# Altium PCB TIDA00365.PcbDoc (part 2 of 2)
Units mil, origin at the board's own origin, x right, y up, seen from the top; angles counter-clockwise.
Board outline 2520 x 2690 mil, 4 copper layers (Top Layer, Mid Layer, GND Layer, Bottom Layer), stack 69.2 mil thick; 170 components, 86 nets, 427 pads, 370 vias.
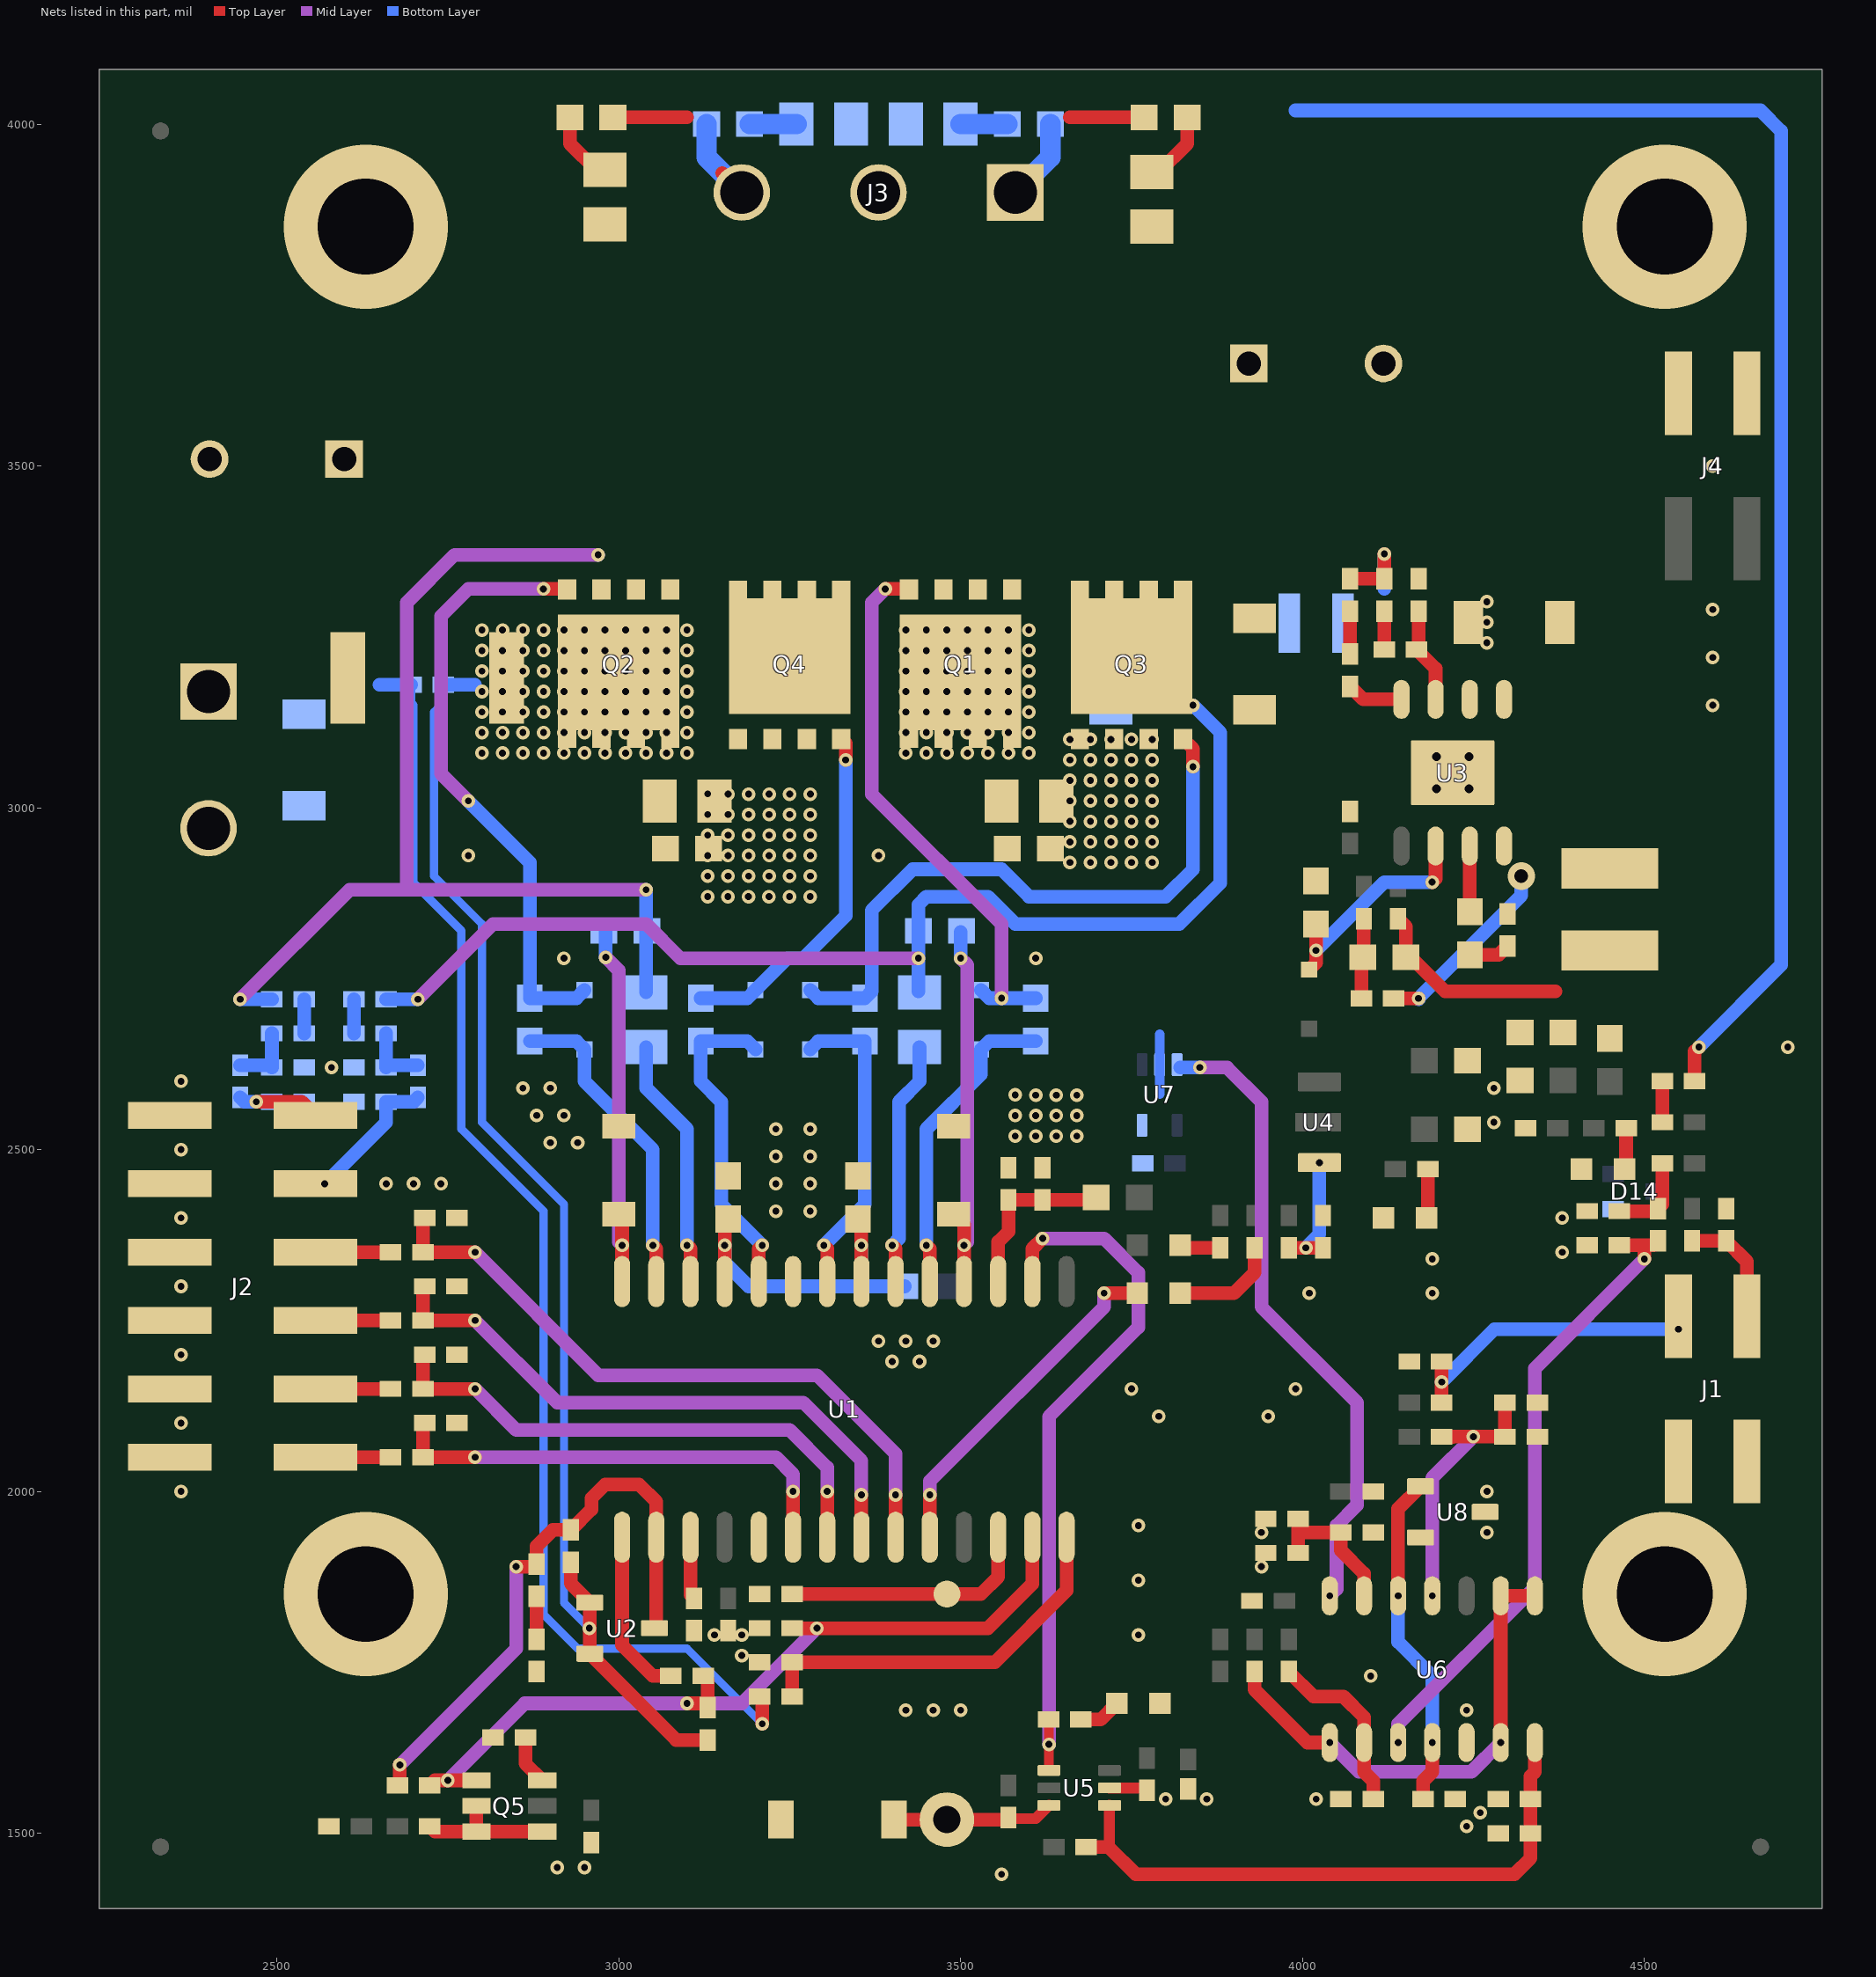
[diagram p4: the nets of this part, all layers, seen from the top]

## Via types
v1: diameter 20, hole 10, Top Layer to Bottom Layer, 355 vias
v2: diameter 40, hole 20, Top Layer to Bottom Layer, 7 vias
v3: diameter 240, hole 140, Top Layer to Bottom Layer, 4 vias
v4: diameter 25.98, hole 12.99, Top Layer to Bottom Layer, tented top, 4 vias

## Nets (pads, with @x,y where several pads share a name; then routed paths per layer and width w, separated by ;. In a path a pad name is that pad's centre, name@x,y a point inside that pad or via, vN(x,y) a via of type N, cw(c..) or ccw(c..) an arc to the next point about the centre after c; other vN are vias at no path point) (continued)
GND: C1.2 C2.2 C3.2 C4.2 C5.2 C10.2 C11.2 C12.2 C13.2 C16.2 C17.1 C18.2 C19.1 C22.1 C23.2 C24.2 C25.2 C26.1 C27.1 C28.1 C29.1 C30.2 C31.2 C32.2 C33.2 C37.2 C38.2 C39.2 C40.2 C41.2 C42.2 C43.2 C44.2 C45.2 C46.2 C47.2 C48.2 C49.2 C50.2 C51.2 D3.2 D4.2 D10.1 D11.1 D12.2 D13.1 D14.1 J1.1 J1.3 J2.1 J2.3 J2.5 J2.7 J2.9 J2.11 J3.2 J4.1 J4.3 J5.2 Q3.1 Q3.2 Q3.3 Q4.1 Q4.2 Q4.3 R10.2 R11.2 R19.1 R20.1 R21.1 R22.1 R24.1 R31.1 R32.1 R48.1 R51.1 R54.1 R61.1 R62.2 R63.1 R71.1 R72.1 SW1.1 U1.5 U1.23 U3.1 U3.9 U5.2 U6.12 U7.2 U7.5 U8.3 | length 145
  Top Layer w16: U5.2@3717.91,1566.38 3770,1566.38 C46.2@3773.62,1562.76
  Bottom Layer w14: 3791.11,2581.11 U7.2@3791.11,2624.24 3791.11,2668.89
  other v1: 3560,1440 2910,1450 2950,1450 4240,1510 4260,1530 3800,1550 3860,1550 4020,1550 3420,1680 3460,1680 3500,1680 4240,1680 4100,1730 3180,1760 3140,1790 3180,1790 3760,1790 3760,1870 3940,1890 3940,1940 4270,1940 3760,1950 2360,2000 4270,2000 2360,2100 3790,2110 3950,2110 3750,2150 3990,2150 3400,2190 3440,2190 2360,2200 3380,2220 3420,2220 3460,2220 4010,2290 4190,2290 2360,2300 4190,2340 4380,2350 2360,2400 4380,2400 3230,2410 3280,2410 2660,2450 2700,2450 2740,2450 3230,2450 3280,2450 3230,2490 3280,2490 2360,2500 2900,2510 2940,2510 3580,2519.74 3609.98,2519.74 3639.98,2519.74 3669.98,2519.74 3230,2530 3280,2530 4280,2540 2880,2550 2920,2550 3580,2549.74 3610,2549.74 3640,2549.74 3670,2549.74 3580,2580 3610,2579.74 3640,2579.74 3670,2579.74 2860,2590 2900,2590 4280,2590 2360,2600 2580,2620 4710,2650 2920,2780 3610,2780 3130,2870 3159.74,2870 3189.74,2870 3219.74,2870 3249.74,2870 3280,2870 3130,2900 3160,2900 3190,2900 3220,2900 3250,2900 3280.26,2900 3660,2920 3689.98,2920 3719.98,2920 3749.98,2920 3780.24,2920 2780,2930 3130,2930 3159.98,2930 3189.98,2930 3219.98,2930 3249.98,2930 3280.24,2930 3380,2930 3660,2950 3689.98,2950 3719.98,2950 3749.98,2950 3780.24,2950 3130,2960 3159.98,2960 3189.98,2960 3219.98,2960 3249.98,2960 3280.24,2960 3660,2980 3690,2980 3720,2980 3750,2980 3780.26,2980 3130,2990 3160,2990 3190,2990 3220,2990 3250,2990 3280.26,2990 3660,3010 3690,3010 3720,3010 3750,3010 3780.26,3010 3130,3020.26 3160,3020 3190,3020 3220,3020 3250,3020 3280.26,3020 3660,3040 3690,3040 3720,3040 3750,3040 3780.26,3040 3660,3070 3690,3070 3720,3070 3750,3070 3780.26,3070 3660,3100 3690,3100 3720,3100 3750,3100 3780.26,3100 4600,3150 4600,3220 4600,3290 4600,3500
  other v3: 2630,1850 4530,1850 2630,3850 4530,3850
  other v4: 4196.18,3027.68 4243.43,3027.68 4196.18,3074.92 4243.43,3074.92
HS_A: C31.1 R30.2 U1.7 | length 792.2
  Top Layer w20: C31.1@2716.38,2200 2713.62,2197.24 R30.2@2713.62,2150 v1(2790,2150) ; U1.7@3305,1932.99 v1(3305,2000)
  Mid Layer w20: v1(2790,2150) 2850,2090 3250,2090 3305,2035 v1(3305,2000)
HS_B: C32.1 R33.2 U1.8 | length 889.4
  Top Layer w20: C32.1@2716.38,2300 2713.62,2297.24 R33.2@2713.62,2250 v1(2790,2250) ; U1.8@3355,1932.99 v1(3355,1995)
  Mid Layer w20: v1(2790,2250) 2910,2130 3270,2130 3355,2045 v1(3355,1995)
HS_BOOT_A: C6.1 U1.26 | length 369.9
  Top Layer w20: v1(3100,2360) 3105,2355 U1.26@3105,2307.01
  Bottom Layer w20: C6.1@3040,2650 3040,2590 3100,2530 v1(3100,2360)
HS_BOOT_B: C7.1 U1.20 | length 361.6
  Top Layer w20: v1(3400,2360) 3405,2355 U1.20@3405,2307.01
  Bottom Layer w20: v1(3400,2360) 3410,2370 3410,2570 3440,2600 C7.1@3440,2650
HS_CSN: C10.1 C11.1 C12.1 C13.1 C20.2 C21.1 Q1.5 Q1.6 Q1.7 Q1.8 Q1.9 Q2.5 Q2.6 Q2.7 Q2.8 Q2.9 R1.1 R15.2 U2.1 U2.2 | length 1895.9
  Top Layer w20: C21.1@2930,1896.38 2930,1865.16 U2.1@2957.76,1837.4 U2.2@2957.76,1762.6 3083.98,1636.38 R15.2@3130,1636.38
  Bottom Layer w12: C20.2@2743.62,3180 2743.62,3153.62 2730,3140 2730,2900 2800,2830 2800,2540 2920,2420 2920,1837.09 v1(2957.09,1800)
  Bottom Layer w20: C20.2@2743.62,3180 2790,3180
  other v1: 2800,3080 2830,3080 2860,3080 2890,3080 2920,3080 2950,3080 2980,3080 3010,3080 3040,3080 3070,3080 3100,3080 3420,3080 3450,3080 3480,3080 3510,3080 3540,3080 3570,3080 3600,3080 2800,3110 2830,3110 2860,3110 2890,3110 2920,3110 2950,3110 2980,3110 3010,3110 3040,3110 3070,3110 3100,3110 3420,3110 3450,3110 3480,3110 3510,3110 3540,3110 3570,3110 3600,3110 2800,3140 2830,3140 2860,3140 2890,3140 2920,3140 2950,3140 2980,3140 3010,3140 3040,3140 3070,3140 3100,3140 3420,3140 3450,3140 3480,3140 3510,3140 3540,3140 3570,3140 3600,3140 2800,3170 2830,3170 2860,3170 2890,3170 2920,3170 2950,3170 2980,3170 3010,3170 3040,3170 3070,3170 3100,3170 3420,3170 3450,3170 3480,3170 3510,3170 3540,3170 3570,3170 3600,3170 2800,3200 2830,3200 2860,3200 2890,3200 2920,3200 2950,3200 2980,3200 3010,3200 3040,3200 3070,3200 3100,3200 3420,3200 3450,3200 3480,3200 3510,3200 3540,3200 3570,3200 3600,3200 2800,3230 2830,3230 2860,3230 2890,3230 2920,3230 2950,3230 2980,3230 3010,3230 3040,3230 3070,3230 3100,3230 3420,3230 3450,3230 3480,3230 3510,3230 3540,3230 3570,3230 3600,3230 2800,3260 2830,3260 2860,3260 2890,3260 2920,3260 2950,3260 2980,3260 3010,3260 3040,3260 3070,3260 3100,3260 3420,3260 3450,3260 3480,3260 3510,3260 3540,3260 3570,3260 3600,3260
HS_CSP: C1.1 C2.1 C3.1 C4.1 C5.1 C20.1 J5.1 L2.1 R1.2 R4.2 R5.2 R14.2 R65.2 | length 4074
  Top Layer w20: v1(3210,1660) R14.2@3210,1696.38 ; R65.2@4573.62,2600 4573.62,2643.62 v1(4580,2650)
  Bottom Layer w12: C20.1@2696.38,3180 2696.38,3153.62 2700,3150 2700,2890 2770,2820 2770,2530 2890,2410 2890,1820 2940,1770 3100,1770 v1(3210,1660)
  Bottom Layer w20: 2650,3180 C20.1@2696.38,3180 ; 3990,4020 4670,4020 4700,3990 4700,2770 v1(4580,2650)
HS_GATE_A: D1.1 R2.1 U1.27 | length 468.1
  Top Layer w20: v1(3050,2360) 3055,2355 U1.27@3055,2307.01
  Bottom Layer w20: R2.1@2870,2658.5 2938.19,2658.5 D1.1@2950,2646.69 2950,2600 3050,2500 v1(3050,2360)
HS_GATE_B: D2.1 R3.1 U1.19 | length 459.8
  Top Layer w20: v1(3450,2360) 3455,2355 U1.19@3455,2307.01
  Bottom Layer w20: v1(3450,2360) 3450,2530 3530,2610 D2.1@3530,2646.69 3541.81,2658.5 R3.1@3610,2658.5
HS_PHASE_A: D3.1 R6.1 U1.28 | length 567.9
  Top Layer w20: D3.1@3000,2405.53 3005,2400.53 v1(3005,2360) U1.28@3005,2307.01
  Mid Layer w20: v1(2981.11,2781.3) 3000,2762.41 3000,2365 v1(3005,2360)
  Bottom Layer w20: v1(2981.11,2781.3) R6.1@2981.11,2817.39
HS_PHASE_B: D4.1 R7.1 U1.18 | length 569.5
  Top Layer w20: D4.1@3490,2405.53 3505,2390.53 v1(3505,2360) U1.18@3505,2307.01
  Mid Layer w20: v1(3500,2780) 3510,2770 3510,2365 v1(3505,2360)
  Bottom Layer w20: v1(3500,2780) R7.1@3500,2818.5
IIN: R21.2 U1.3 | length 84.4
  Top Layer w20: R21.2@3105,1848.62 U1.3@3105,1932.99
IOUT: I_CS1.1 R20.2 U1.12 | length 369.7
  Top Layer w20: R20.2@3253.62,1850 3530,1850 3555,1875 U1.12@3555,1932.99
LS_A: C30.1 R29.2 U1.6 | length 694.9
  Top Layer w20: C30.1@2716.38,2100 2713.62,2097.24 R29.2@2713.62,2050 v1(2790,2050) ; U1.6@3255,1932.99 v1(3255,2000)
  Mid Layer w20: v1(2790,2050) 3230,2050 3255,2025 v1(3255,2000)
LS_B: C33.1 R34.2 U1.9 | length 986.7
  Top Layer w20: C33.1@2716.38,2400 2713.62,2397.24 R34.2@2713.62,2350 v1(2790,2350) ; U1.9@3405,1932.99 v1(3405,1995)
  Mid Layer w20: v1(2790,2350) 2970,2170 3290,2170 3405,2055 v1(3405,1995)
LS_GATE_A: D5.1 R8.1 U1.24 | length 475.9
  Top Layer w20: U1.24@3205,2307.01 3205,2355.29 3205.29,2355.29 v1(3210,2360)
  Bottom Layer w20: D5.1@3200,2646.69 3188.19,2658.5 R8.1@3120,2658.5 3120,2600 3150,2570 3150,2420 v1(3210,2360)
LS_GATE_B: D6.1 R9.2 U1.22 | length 463.3
  Top Layer w20: v1(3300,2360) 3305,2355 U1.22@3305,2307.01
  Bottom Layer w20: D6.1@3280,2646.69 3291.81,2658.5 R9.2@3360,2658.5 3360,2420 v1(3300,2360)
NetC8_1: C8.1 R4.1 | length 105.9
  Top Layer w20: C8.1@2928.5,4010 2928.5,3971.5 2966.8,3933.2 R4.1@2980,3933.2
NetC9_1: C9.1 R5.1 | length 107.3
  Top Layer w20: R5.1@3780,3930 3790.19,3930 3831.5,3971.3 C9.1@3831.5,4010
NetC14_1: C14.1 R10.1 | length 68.5
  Bottom Layer w30: C14.1@3191.5,4000 R10.1@3260,4000
NetC15_1: C15.1 R11.1 | length 68.5
  Bottom Layer w30: R11.1@3500,4000 C15.1@3568.5,4000
NetC16_1: C16.1 C18.1 R12.1 U1.17 | length 255.6
  Top Layer w20: U1.17@3555,2307.01 3555,2365 3570,2380 C16.1@3570,2426.38 C18.1@3620,2426.38 3694.88,2426.38 R12.1@3698.5,2430
NetC17_2: C17.2 C19.2 R13.1 U1.21 U1.25 | length 545.1
  Top Layer w20: U1.25@3155,2307.01 v1(3155,2360) 3155,2393.5 C17.2@3160,2398.5 ; C19.2@3350,2398.5 3355,2393.5 v1(3355,2360) U1.21@3355,2307.01
  Bottom Layer w20: v1(3155,2360) 3155,2335 3190,2300 R13.1@3418.5,2300 ; 3355,2305 v1(3355,2360)
NetC26_2: C26.2 J2.4 R35.1 | length 258.8
  Top Layer w20: J2.4@2537.5,2450 J2.4@2590,2450
  Bottom Layer w20: v1(2570,2450) 2660,2540 C26.2@2660,2570 2700,2570 R35.1@2706.38,2576.38
NetC27_2: C27.2 J2.2 R36.1 | length 143.6
  Top Layer w20: v1(2470,2570) 2536.3,2570 J2.2@2556.3,2550
  Bottom Layer w20: R36.1@2446.38,2576.38 2452.76,2570 v1(2470,2570) C27.2@2492.76,2570
NetC28_2: C28.2 J1.4 R37.1 | length 191.4
  Top Layer w20: R37.1@4570,2366.38 C28.2@4620,2366.38 4650,2336.38 J1.4@4650,2237.4
NetC29_2: C29.2 J1.2 R38.1 | length 438.4
  Top Layer w20: R38.1@4203.62,2130 v1(4203.62,2160) C29.2@4203.62,2190
  Bottom Layer w20: v1(4203.62,2160) 4281.02,2237.4 v1(4550,2237.4)
NetC34_1: C34.1 C37.1 L1.2 R43.1 R44.2 | length 300.4
  Top Layer w20: R44.2@4139.8,2837.68 4151.3,2826.18 C34.1@4151.3,2781.3 4158.7,2781.3 4208.7,2731.3 4369.8,2731.3
NetC34_2: C34.2 C36.1 R42.2 | length 117.9
  Top Layer w20: R42.2@4086.18,2721.3 4086.18,2779.17 C34.2@4088.31,2781.3 4089.8,2782.79 C36.1@4089.8,2837.68
NetC35_1: C35.1 U3.7 | length 96.2
  Top Layer w20: C35.1@4244.8,2847.8 U3.7@4244.8,2944.02
NetC35_2: C35.2 R41.1 | length 60.3
  Top Layer w20: C35.2@4244.8,2784.8 4286.93,2784.8 R41.1@4299.8,2797.68
NetC40_1: C40.1 L2.2 R46.1 R49.1 U3.2 | length 137.5
  Top Layer w20: R46.1@4069.8,3334.92 R49.1@4119.8,3334.92 v1(4119.8,3371.3)
  Bottom Layer w20: 4119.8,3320.2 v1(4119.8,3371.3)
  other v1: 4269.8,3241.3 4269.8,3271.3 4269.8,3301.3
NetC41_1: C41.1 D9.1 U3.6 | length 336.7
  Top Layer w20: D9.1@4010,2763.31 4019.8,2773.11 v1(4019.8,2791.38) C41.1@4019.8,2829.8 ; v1(4189.8,2891.3) 4194.8,2896.3 U3.6@4194.8,2944.02
  Bottom Layer w20: v1(4019.8,2791.38) 4119.73,2891.3 v1(4189.8,2891.3)
NetC45_1: C45.1 R60.2 R61.2 U6.4 | length 385.1
  Top Layer w20: 4220.39,2079.35 4219.74,2080 v1(4250,2080) R61.2@4296.38,2080 C45.1@4296.38,2130
  Mid Layer w20: v1(4190,1847.28) 4190,2020 v1(4250,2080)
NetC47_1: C47.1 R59.1 R63.2 U5.1 U6.14 | length 908.2
  Top Layer w16: 3717.91,1478.46 U5.1@3717.91,1540.79
  Top Layer w20: R59.1@3683.62,1480 3716.38,1480 ; 3717.91,1478.46 3756.38,1440 4310,1440 4333.62,1463.62 R63.2@4333.62,1500 C47.1@4333.62,1550 4333.62,1583.62 4340,1590 U6.14@4340,1632.72
NetD1_2: D1.2 Q2.4 R2.2 | length 898.6
  Top Layer w20: v1(2889.96,3320) 2923.81,3320 Q2.4@2924.51,3319.3
  Mid Layer w20: v1(2780,3010) 2740,3050 2740,3280 2780,3320 v1(2889.96,3320)
  Bottom Layer w20: v1(2780,3010) 2870,2920 R2.2@2870,2721.5 2938.19,2721.5 D1.2@2950,2733.31
NetD2_2: D2.2 Q1.4 R3.2 | length 805.2
  Top Layer w20: v1(3389.96,3320) 3423.81,3320 Q1.4@3424.51,3319.3
  Mid Layer w20: v1(3389.96,3320) 3370,3300.04 3370,3020 3560,2830 3560,2731.5 v1(3560,2721.5)
  Bottom Layer w20: D2.2@3530,2733.31 3541.81,2721.5 v1(3560,2721.5) R3.2@3610,2721.5
NetD5_2: D5.2 Q4.4 R8.2 | length 523.3
  Top Layer w20: Q4.4@3325.49,3100.7 3331.97,3094.22 v1(3331.97,3070)
  Bottom Layer w20: R8.2@3120,2721.5 3188.19,2721.5 D5.2@3200,2733.31 3246.69,2780 3270,2780 3331.97,2841.97 v1(3331.97,3070)
NetD6_2: D6.2 Q3.4 R9.1 | length 942.2
  Top Layer w20: Q3.4@3825.49,3100.7 3840,3086.19 v1(3840,3060)
  Bottom Layer w20: D6.2@3280,2733.31 3291.81,2721.5 R9.1@3360,2721.5 3370,2731.5 3370,2850 3430,2910 3560,2910 3600,2870 3800,2870 3840,2910 v1(3840,3060)
NetD7_2: D7.2 R39.1 | length 157.3
  Top Layer w20: D7.2@3821.5,2290 3900,2290 3930,2320 R39.1@3930,2356.38
NetD8_2: D8.2 R40.1 | length 60
  Top Layer w20: D8.2@3821.5,2360 3825.12,2356.38 R40.1@3880,2356.38
NetD10_2: D10.2 R45.1 | length 60.9
  Top Layer w20: D10.2@4471.3,2471.3 4473.43,2473.43 R45.1@4473.43,2531.3
NetD11_2: D11.2 R53.1 | length 66.4
  Top Layer w20: D11.2@4183.43,2404.92 R53.1@4183.43,2471.3
NetD13_2: D13.2 R64.2 | length 62.4
  Top Layer w20: R64.2@3675.91,1666.38 3704.88,1666.38 D13.2@3728.5,1690
NetJ2_6: J2.6 R34.1 | length 128.9
  Top Layer w20: J2.6@2537.5,2350 R34.1@2666.38,2350
NetJ2_8: J2.8 R33.1 | length 128.9
  Top Layer w20: J2.8@2537.5,2250 R33.1@2666.38,2250
NetJ2_10: J2.10 R30.1 | length 128.9
  Top Layer w20: J2.10@2537.5,2150 R30.1@2666.38,2150
NetJ2_12: J2.12 R29.1 | length 128.9
  Top Layer w20: J2.12@2537.5,2050 R29.1@2666.38,2050
NetL1_1: L1.1 R41.2 R42.1 U3.8 | length 278.1
  Top Layer w20: R42.1@4133.43,2721.3 v1(4169.8,2721.3)
  Bottom Layer w20: v1(4169.8,2721.3) 4320,2871.5 v2(4320,2900) ; v1@4170,2720 v1@4170.55,2720.55
NetQ5_2: Q5.2 Q5.3 Q5.4 R23.1 | length 205.1
  Top Layer w20: R23.1@2723.62,1510 2731.02,1502.6 Q5.3@2791.77,1502.6 ; Q5.2@2791.77,1540 Q5.3@2791.77,1502.6 ; Q5.4@2888.23,1502.6 Q5.3@2791.77,1502.6
NetQ5_6: Q5.6 R24.2 | length 72.8
  Top Layer w20: R24.2@2863.62,1640 2863.62,1602.01 Q5.6@2888.23,1577.4
NetR18_2: R18.2 R19.2 | length 62.8
  Top Layer w20: R19.2@2880,1783.62 R18.2@2880,1846.38
NetR25_1: R25.1 R27.2 | length 50
  Bottom Layer w20: R27.2@2612.76,2670 R25.1@2612.76,2720
NetR26_1: R26.1 R28.2 | length 50
  Bottom Layer w20: R28.2@2540,2670 R26.1@2540,2720
NetR27_1: R27.1 R31.2 R35.2 | length 92.8
  Bottom Layer w20: R31.2@2660,2620 R27.1@2660,2670 ; R31.2@2663.62,2623.62 R35.2@2706.38,2623.62
NetR28_1: R28.1 R32.2 R36.2 | length 92.8
  Bottom Layer w20: R36.2@2446.38,2623.62 R32.2@2489.13,2623.62 ; R32.2@2492.76,2620 R28.1@2492.76,2670
NetR46_2: R46.2 R47.1 | length 62.8
  Top Layer w20: R47.1@4069.8,3224.92 R46.2@4069.8,3287.68
NetR47_2: R47.2 U3.4 | length 82.9
  Top Layer w20: R47.2@4069.8,3177.68 4088.9,3158.58 U3.4@4144.8,3158.58
NetR49_2: R49.2 R50.1 | length 56.4
  Top Layer w20: R50.1@4119.8,3231.3 R49.2@4119.8,3287.68
NetR50_2: R50.2 R51.2 U3.3 | length 141.7
  Top Layer w20: R51.2@4169.8,3287.68 4169.8,3234.06 R50.2@4167.05,3231.3 4194.8,3203.54 U3.3@4194.8,3158.58
NetR52_1: R52.1 R54.2 U4.1 | length 182.8
  Top Layer w20: R52.1@3980,2356.38 v1(4005,2356.38) R54.2@4030,2356.38
  Bottom Layer w20: v1(4005,2356.38) 4024.8,2376.18 v1(4024.8,2480.94)
NetR57_2: R57.2 U6.1 U6.2 U6.8 U6.13 | length 718.3
  Top Layer w20: R57.2@3930,1736.38 3930,1710 4007.28,1632.72 v1(4040,1632.72) ; v1(4290,1632.72) U6.2@4290,1847.28 U6.1@4340,1847.28
  Mid Layer w20: v1(4040,1632.72) 4082.72,1590 4247.28,1590 v1(4290,1632.72)
NetR58_2: R58.2 R62.1 U6.9 | length 263.1
  Top Layer w20: R58.2@3980,1736.38 4016.38,1700 4060,1700 4090,1670 U6.9@4090,1632.72 4090,1590 4103.62,1576.38 R62.1@4103.62,1550
NetR65_1: R65.1 R66.2 | length 60
  Top Layer w20: R66.2@4526.38,2540 R65.1@4526.38,2600
NetR69_1: R69.1 R70.2 R72.2 | length 126.9
  Top Layer w20: R72.2@4463.62,2410 4516.38,2410 R70.2@4520,2413.62 4526.38,2420 R69.1@4526.38,2480
NetU6_7: U6.7 U7.3 | length 936.8
  Mid Layer w20: v1(3850,2620) 3890,2620 3940,2570 3940,2270 4080,2130 4080,1980 4050,1950 4050,1857.28 v1(4040,1847.28)
  Bottom Layer w20: U7.3@3821.23,2620 v1(3850,2620)
OVS: R64.1 U1.16 U5.4 | length 1048.5
  Top Layer w14: U5.4@3629.33,1591.97 v1(3629.33,1630) R64.1@3629.33,1666.38
  Top Layer w20: U1.16@3605,2307.01 3605,2355 v1(3620,2370)
  Mid Layer w20: v1(3620,2370) 3710,2370 3760,2320 3760,2240 3629.33,2109.33 v1(3629.33,1630)
PGOOD: D7.1 U1.10 | length 511.1
  Top Layer w20: U1.10@3455,1932.99 v1(3455,1995) ; v1(3710,2290) D7.1@3758.5,2290
  Mid Layer w20: v1(3455,1995) 3455,2015 3710,2270 v1(3710,2290)
PHASEA: C6.2 C8.2 C14.2 J3.3 Q2.1 Q2.2 Q2.3 Q4.5 Q4.6 Q4.7 Q4.8 Q4.9 R6.2 R26.2 | length 1854.6
  Top Layer w20: C8.2@2991.5,4010 3100.02,4010 ; J3.3@3151.5,3928.5 J3.3@3180,3900
  Mid Layer w20: v1(2446.38,2720) 2606.38,2880 v1(3040,2880) ; 2690,2880 2690,3300 2760,3370 v1(2970,3370)
  Bottom Layer w20: v1(2446.38,2720) R26.2@2492.76,2720 ; C6.2@3040,2730 3040,2818.5 R6.2@3041.5,2820 ; R6.2@3040,2821.5 v1(3040,2880)
  Bottom Layer w30: C14.2@3128.5,4000 3128.5,3951.5 J3.3@3180,3900
PHASEB: C7.2 C9.2 C15.2 J3.1 Q1.1 Q1.2 Q1.3 Q3.5 Q3.6 Q3.7 Q3.8 Q3.9 R7.2 R25.2 | length 2006.2
  Top Layer w20: J3.1@3580,3900 J3.1@3608.5,3928.5 ; 3659.98,4010 C9.2@3768.5,4010
  Mid Layer w20: v1(2706.38,2720) 2816.38,2830 3040,2830 3090,2780 v1(3438.5,2780)
  Bottom Layer w20: R25.2@2660,2720 v1(2706.38,2720) ; C7.2@3438.5,2731.5 v1(3438.5,2780) R7.2@3438.5,2820 3438.5,2858.5 3450,2870 3540,2870 3580,2830 3820,2830 3880,2890 3880,3110 v1(3840,3150)
  Bottom Layer w30: J3.1@3580,3900 3631.5,3951.5 C15.2@3631.5,4000
PROT_VTH: C49.1 R67.1 R68.2 U6.5 U6.11 U8.1 U8.2 | length 500
  Top Layer w20: v1(4140,1847.28) 4140,1974.65 U8.1@4172.76,2007.4 ; C49.1@4176.38,1550 4176.38,1576.38 4190,1590 v1(4190,1632.72)
  Bottom Layer w20: v1@4140,1850 v1(4140,1847.28) 4140,1780 4190,1730 v1(4190,1632.72)
RESET: R55.1 SW1.2 TP1.1 U5.6 | length 235.3
  Top Layer w16: R55.1@3571.38,1521.38 3609.92,1521.38 U5.6@3629.33,1540.79
  Top Layer w20: SW1.2@3402.68,1520 TP1.1@3480,1520 3570,1520 R55.1@3571.38,1521.38
SIA: R17.1 U1.1 | length 248
  Top Layer w20: U1.1@3005,1932.99 3005,1775 3050,1730 R17.1@3076.38,1730
SIB: C22.2 R14.1 U1.14 | length 572.9
  Top Layer w20: R14.1@3253.62,1700 C22.2@3253.62,1750 3550,1750 3655,1855 U1.14@3655,1932.99
SOA: C21.2 R16.1 R18.1 U1.2 U2.3 | length 868.2
  Top Layer w20: R16.1@2676.38,1570 2680,1573.62 v1(2680,1600) ; v1(2850,1890) 2876.38,1890 R18.1@2880,1893.62 2880,1920 2903.62,1943.62 C21.2@2930,1943.62 2960,1973.62 2960,1990 2980,2010 3030,2010 3055,1985 U1.2@3055,1932.99 3055,1802.76 U2.3@3052.24,1800
  Mid Layer w20: v1(2680,1600) 2850,1770 v1(2850,1890)
SOB: C23.1 Q5.1 R15.1 R16.2 R17.2 U1.13 | length 1231.4
  Top Layer w20: R16.2@2723.62,1570 2731.02,1577.4 v1(2750,1577.4) Q5.1@2791.77,1577.4 ; v1(3100,1690) 3123.62,1690 R15.1@3130,1683.62 3130,1723.62 R17.2@3123.62,1730 ; C23.1@3253.62,1800 v1(3290,1800) 3540,1800 3605,1865 U1.13@3605,1932.99
  Mid Layer w20: v1(2750,1577.4) 2862.6,1690 v1(3100,1690) 3180,1690 v1(3290,1800)
TEMP_VTH: C50.1 R68.1 R71.2 U6.6 | length 203
  Top Layer w20: R71.2@3993.62,1910 3993.62,1940 ; C50.1@3993.62,1960 3993.62,1940 ; 4040,1940 3993.62,1940 ; R68.1@4056.38,1940 4056.38,1913.62 4090,1880 U6.6@4090,1847.28
VBUS_SENSE: C51.1 R70.1 U6.10 | length 926.4
  Top Layer w20: C51.1@4463.62,2360 R70.1@4513.62,2360 ; v1(4500,2340) 4500,2360
  Mid Layer w20: v1(4140,1632.72) 4140,1660 4340,1860 4340,2180 v1(4500,2340)
pads on no net: FID1.1 FID2.1 FID3.1 FID4.1 FID5.1 FID6.1 U7.1

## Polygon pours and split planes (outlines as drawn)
PROT_VTH on Top Layer "PROT_VTH_L01_P044" (solid, remove dead copper, pour order 44): 4090,1930 4090,2020 4200,2020 4200,1920 4160,1920 4140,1900 4110,1930
PHASEB on Top Layer "PHASEB_L01_P055" (solid, remove dead copper, pour order 55): 3410,3830 3480,3900 3480,4050 3640,4050 3680,4010 3680,3570 3850,3400 3850,3140 3650,3140 3650,3280 3630,3300 3460,3300 3460,3370 3410,3420
PHASEA on Top Layer "PHASEA_L01_P056" (solid, remove dead copper, pour order 56): 2960,3300 3130,3300 3150,3280 3150,3140 3350,3140 3350,3830 3280,3900 3280,4050 3120,4050 3080,4010 3080,3780 2960,3660
HS_CSN on Top Layer "HS_CSN_L01_P054" (solid, remove dead copper, pour order 54): 3400,3280 3620,3280 3620,3060 3590,3060 3590,2920 3450,2920 3400,2970 3400,3060
HS_CSN on Top Layer "HS_CSN_L01_P057" (solid, remove dead copper, pour order 57): 2780,3280 3120,3280 3120,3100 3120,3060 3090,3060 3090,2920 2920,2920 2780,3060
GND on Top Layer "GND_L01_P115" (solid, remove dead copper, pour order 115): 2270,1420 4730,1420 4730,4050 2270,4050
+12V on Top Layer "+12V_L01_P064" (solid, remove dead copper, pour order 64): 4359.8,2521.3 4359.8,2621.3 4469.8,2621.3 4469.8,2571.3 4449.8,2551.3 4449.8,2521.3
+3V3 on Top Layer "+3V3_L01_P045" (solid, remove dead copper, pour order 45): 4120,2460 4120,2510 4100,2510 4100,2560 4150,2560 4200,2560 4200,2510 4160,2510 4150,2500 4150,2460
NetC34_1 on Top Layer "NETC34_1_L01_P073" (solid, remove dead copper, pour order 73): 4339.8,2831.3 4339.8,2741.3 4359.8,2721.3 4359.8,2651.3 4419.8,2651.3 4429.8,2641.3 4479.8,2641.3 4559.8,2721.3 4559.8,2831.3
NetL1_1 on Top Layer "NETL1_1_L01_P067" (solid, remove dead copper, pour order 67): 4289.8,2831.3 4309.8,2831.3 4309.8,2861.3 4319.8,2871.3 4359.8,2871.3 4559.8,2871.3 4559.8,2971.3 4549.8,2981.3 4289.8,2981.3 4279.8,2971.3 4279.8,2881.3 4289.8,2871.3
NetC40_1 on Top Layer "NETC40_1_L01_P052" (solid, remove dead copper, pour order 52): 4239.8,3131.3 4229.8,3141.3 4229.8,3210.2 4209.8,3230.2 4209.8,3311.3 4229.8,3331.3 4268.7,3331.3 4289.8,3310.2 4289.8,3239.8 4259.8,3209.8 4259.8,3141.3 4249.8,3131.3
+12V on Top Layer "+12V_L01_P074" (solid, remove dead copper, pour order 74): 3995.24,2588.39 4200,2588.39 4200,2686.16 3995.24,2686.16
HS_CSP on Top Layer "HS_CSP_L01_P058" (solid, remove dead copper, pour order 58): 2270,3080 2660,3080 2660,3190 2690,3220 3550,3220 3700,3220 4000,3220 4010,3230 4010,4050 2270,4050
HS_CSP on Bottom Layer "HS_CSP_L04_P063" (solid, remove dead copper, pour order 63): 2270,3080 2660,3080 2660,3190 2660,3220 2690,3220 3550,3220 3700,3220 4000,3220 4010,3220 4010,3230 4010,4050 2270,4050
GND on Bottom Layer "GND_L04_P077" (solid, remove dead copper, pour order 77): 2270,1420 4730,1420 4730,4050 2270,4050
NetC40_1 on Bottom Layer "NETC40_1_L04_P065" (solid, remove dead copper, pour order 65): 4040,3210 4030,3220 4030,3320 4040,3330 4270,3330 4290,3310 4290,3230 4270,3210
HS_CSN on Bottom Layer "HS_CSN_L04_P053" (solid, remove dead copper, pour order 53): 3620,3280 3620,3060 2780,3060 2780,3280
GND on Bottom Layer "GND_L04_P043" (solid, remove dead copper, pour order 43): 3450,4050 3450,3950 3470,3930 3470,3860 3450,3840 3310,3840 3290,3860 3290,3930 3310,3950 3310,4050
HS_CSN on Mid Layer "HS_CSN_L02_P050" (solid, remove dead copper, pour order 50): 3610,3060 3620,3070 3620,3263.51 3620,3270 3610,3280 3410,3280 3400,3270 3400,3070 3410,3060
HS_CSN on Mid Layer "HS_CSN_L02_P051" (solid, remove dead copper, pour order 51): 2780,3270 2790,3280 3110,3280 3120,3270 3120,3070 3110,3060 2790,3060 2780,3070
GND on Mid Layer "GND_L02_P079" (solid, remove dead copper, pour order 79): 2270,1420 4730,1420 4730,4050 2270,4050
HS_CSN on GND Layer "HS_CSN_L03_P048" (solid, remove dead copper, pour order 48): 3610,3060 3620,3070 3620,3263.51 3620,3270 3610,3280 3410,3280 3400,3270 3400,3070 3410,3060
HS_CSN on GND Layer "HS_CSN_L03_P049" (solid, remove dead copper, pour order 49): 2780,3270 2790,3280 3110,3280 3120,3270 3120,3070 3110,3060 2790,3060 2780,3070
GND on GND Layer "GND_L03_P078" (solid, remove dead copper, pour order 78): 2270,1420 4730,1420 4730,4050 2270,4050
HS_CSN on Bottom Paste "NONET_L04_P125" (solid, pour order 47): 3620,3280 3620,3060 2780,3060 2780,3280
no net on Bottom Paste "Bottom Paste-No Net" (solid): 4280,3110 4160,3110 4160,2990 4280,2990
HS_CSN on Solder Side "NONET_L04_P127" (solid, pour order 46): 3620,3280 3620,3060 2780,3060 2780,3280
no net on Solder Side "Solder Side-No Net" (solid): 4280,2990 4160,2990 4160,3110 4280,3110

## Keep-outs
Keep-Out Layer:
  lines w10: 2230,1380 4770,1380 4770,4090 2230,4090 2230,1380
  text ".Layer_Name" at 577,-858.49 h60

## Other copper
Top Layer:
  pour cut-out: 3728.5,3885 3700.39,3885 3700,3885.39 3700,3910 3720,3910 3730,3900
  pour cut-out: 3031.5,3888.2 3059.61,3888.2 3059.61,3909.61 3060,3910 3030,3910
  pour cut-out: 3360,3830 3400,3830 3400,3820 3360,3820
  pour cut-out: 4590,2174.96 4610,2174.96 4610,2190 4590,2190
  text ".Layer_Name" at 577,-858.49 h60
Bottom Layer:
  pour cut-out: 3220,2620 3225.12,2614.88 3254.88,2614.88 3260,2620
  pour cut-out: 3670,4030 3670,4060 3660,4060 3660,4030
  pour cut-out: 3090,4030 3090,4060 3100,4060 3100,4030
  pour cut-out: 3530,3840 3470,3840 3480,3850 3530,3850
  pour cut-out: 3280,3850 3200,3850 3210,3860 3280,3860
  text ".Layer_Name" at 577,-858.49 h60

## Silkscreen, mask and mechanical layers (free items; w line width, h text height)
Top Overlay:
  text "Full-Bridge / Power Stage" at 4460,3420 h50 r90
  text "+" at 2270,3280 h72.83
  text "+3.3V /  / +12V" at 4800,3130 h40 r90
  text "-" at 2270,2780 h72.83
  text "12V" at 4244.72,2430.81 h30
  text "3.3V" at 4214.86,2360.99 h30
  text "FAULT" at 3873.76,2259.84 h30
  text "PGOOD" at 3874.88,2200.76 h30
  text "CS / DC_Link" at 4620,2030 h40 r90
  text "TRIP" at 3704.87,1720.72 h30
  text "CLR_FLT" at 3243.18,1586.25 h40
  text "PH_A / PH_B / LS_B / HS_B / HS_A / LS_A" at 2310,1530 h40
  text ".Layer_Name" at 577,-858.49 h60
Bottom Overlay:
  text ".Layer_Name" at 577,-858.49 h60
Top Paste:
  text ".Layer_Name" at 577,-858.49 h60
Bottom Paste:
  text ".Layer_Name" at 577,-858.49 h60
Top Solder:
  text ".Layer_Name" at 577,-858.49 h60
  text ".Layer_Name" at 577,-858.49 h60
Solder Side:
  text ".Layer_Name" at 577,-858.49 h60
Drill Guide:
  text ".Layer_Name" at 577,-858.49 h60
Mechanical 1:
  the board outline again, w10
  text ".Layer_Name" at 577,-858.49 h60
Mechanical 2:
  rectangle: 125,-400 500,-275
  rectangle: 0,-275 125,-150
  lines w7: 0,-275 1000,-275 ; 125,-400 125,-150 ; 250,-400 250,-150 ; 500,-400 500,-150 ; 750,-400 750,-150 ; 0,-400 0,-150 1000,-150 1000,-400 0,-400
  text ".Layer_Name" at 577,-858.49 h60
Mechanical 3:
  text ".Layer_Name" at 577,-858.49 h60
Mechanical 4:
  text ".Layer_Name" at 577,-858.49 h60
Mechanical 5:
  lines w10: -292,-930.17 6308,-930.17 ; -292,-726.83 6310,-726.83 ; -292,-523.5 -292,-1133.5 3713,-1133.5 6310,-1133.5 6310,-523.5 -291.5,-523.5 -291.5,-1133.5 1284,-1133.5 ; 2173,-1133.5 2173,-523.5 ; 3440,-726.83 3440,-523.5 ; 4280,-726.83 4280,-523.5 ; 4902,-1140 4902,-937.17
  text "COMPONENTS MARKED 'DNP' SHOULD NOT BE POPULATED." at 1153.5,-318.5 h60
  text "ASSEMBLY VARIANT:" at 1153,-434 h60
  text ".VariantName" at 2189,-434 h60
  text "PCB VIEWED FROM TOP SIDE" at -228.5,-655.67 h60
  text "BOARD #:" at 2248,-655.67 h60
  text ".PRJ_Number" at 2793.5,-655.67 h60
  text "REV:" at 3638,-655.67 h60
  text ".PCB_Rev" at 3929.5,-655.67 h60
  text "SVN REV:" at 4476,-655.67 h60
  text ".VersionControl_RevNumber" at 4982,-655.67 h60
  text "TID #:" at 2248,-859 h60
  text ".TID" at 2793.5,-859 h60
  text "PLOT NAME =" at -228.5,-1064.34 h60
  text ".plot_File_Name" at 577,-1064.34 h60
  text "GENERATED    :" at 2250,-1064.34 h60
  text ".Print_Date" at 3119.5,-1064.34 h60
  text ".Print_Time" at 3848.5,-1064.34 h60
  text "TEXAS INSTRUMENTS" at 5113,-1064.34 h60
Mechanical 6:
  lines w10: -292.5,-727.33 6309.5,-727.33 ; -290.5,-930.67 6309.5,-930.67 ; 1115.5,-1140.5 1115.5,-937.67 ; 1737.5,-727.33 1737.5,-524 ; 2577.5,-727.33 2577.5,-524 ; 3844.5,-1134 3844.5,-524 ; 4733.5,-1134 6309,-1134 6309,-524 -292.5,-524 -292.5,-1134 2304.5,-1134 6309.5,-1134 6309.5,-524
  text "COMPONENTS MARKED 'DNP' SHOULD NOT BE POPULATED." at 6102,-318 h60
  text ".VariantName" at 5058,-434 h60
  text "ASSEMBLY VARIANT:" at 6097,-434 h60
  text ".VersionControl_RevNumber" at 1035.5,-656.17 h60
  text "SVN REV:" at 1541.5,-656.17 h60
  text ".PCB_Rev" at 2088,-656.17 h60
  text "REV:" at 2379.5,-656.17 h60
  text ".PRJ_Number" at 3224,-656.17 h60
  text "BOARD #:" at 3769.5,-656.17 h60
  text "PCB VIEWED FROM BOTTOM SIDE" at 6246,-656.17 h60
  text ".TID" at 3224,-859.5 h60
  text "TID #:" at 3769.5,-859.5 h60
  text "TEXAS INSTRUMENTS" at 904.5,-1064.84 h60
  text ".Print_Time" at 2169,-1064.84 h60
  text ".Print_Date" at 2898,-1064.84 h60
  text "GENERATED    :" at 3767.5,-1064.84 h60
  text ".plot_File_Name" at 5440.5,-1064.84 h60
  text "PLOT NAME =" at 6246,-1064.84 h60
Mechanical 9:
  drawing of 57 lines, arcs and shapes, not listed
  text "1" at 739.84,8036.5 h70
  text "2" at 3235.5,8036.5 h70
  text "3" at 5724.84,8036.5 h70
  text "4" at 8231.51,8036.5 h70
  text "5" at 10730.5,8036.5 h70
  text "6" at 13235.5,8036.5 h70
  text "A" at -416.5,6893.5 h70
  text "A" at 14383.5,6893.5 h70
  text "B" at -416.5,4513.5 h70
  text "B" at 14383.5,4513.5 h70
  text "C" at -416.5,2138.5 h70
  text "C" at 14383.5,2138.5 h70
  text "PROJECT TITLE:" at 11343.5,277.5 h45
  text ".PRJ_Title" at 11393.5,144.17 h70
  text "DESIGNED FOR:" at 11343.5,-23.5 h45
  text ".PRJ_Customer" at 11393.5,-163.5 h70
  text "D" at -416.5,-231.5 h70
  text "D" at 14383.5,-231.5 h70
  text "FILE NAME:" at 11343.5,-323.5 h45
  text ".PCB_File_Name_No_Path" at 11393.5,-443.5 h70
  text "Texas Instruments (TI) and/or its licensors do not warrant the accuracy or completeness of this specification" at 6374,-605.34 h45
  text "ENGINEER:" at 11343.5,-613.5 h45
  text "LAYOUT BY:" at 12848.5,-613.5 h45
  text "or any information contained therein. TI and/or its licensors do not warrant that this design will meet" at 6329.01,-718 h45
  text ".PRJ_Engineer" at 11393.5,-768.49 h70
  text ".PCB_Layout" at 12899,-768.49 h70
  text "the specifications, will be suitable for your application or fit for any particular purpose, or will operate in" at 6329.01,-830.67 h45
  text ".Layer_Name" at 577,-858.49 h60
  text "ALTIUM DESIGNER VERSION:" at 12848.5,-923.5 h45
  text "an implementation. TI and/or its licensors do not warrant that the design is production worthy. You should" at 6329.01,-943.33 h45
  text "completely validate and test your design implementation to confirm the system functionality for your application." at 6374,-1056 h45
  text ".print_Scale" at 11393.5,-1056.83 h70
  text ".Application_BuildNumber" at 12899,-1056.83 h70
  text "1" at 739.84,-1263.5 h70
  text "2" at 3235.5,-1263.5 h70
  text "3" at 5724.84,-1263.5 h70
  text "4" at 8231.51,-1263.5 h70
  text "5" at 10730.5,-1263.5 h70
  text "6" at 13235.5,-1263.5 h70
Mechanical 10:
  drawing of 189 lines, arcs and shapes, not listed
  text "DESIGN INFORMATION" at 12381.02,6028 h60
  text "MIN. TRACK WIDTH:" at 11736.46,5848 h60
  text "8" at 12832.7,5848 h60
  text "MIL" at 12987.46,5848 h60
  text "MIN. CLEARANCE:" at 11736.46,5716 h60
  text "0.2" at 12772.7,5716 h60
  text "mm" at 12987.46,5716 h60
  text "MIN. VIA PAD SIZE:" at 11736.46,5584 h60
  text "24" at 12802.71,5584 h60
  text "MIL" at 12987.46,5584 h60
  text "0.05mm (2MIL)" at 12431.46,5442.29 h60
  text "MINIMUM ANNULAR RING" at 11407.23,5438 h60
  text "EXTERNAL" at 13139.46,5438 h60
  text "PER" at 11607.23,5320 h60
  text "IPC-D-275 CLASS 2 LEVEL C" at 11827.23,5320 h60
  text "MIL, HOLES" at 13315.46,5207.71 h60
  text "+/-" at 12923,5207 h60
  text "+/-" at 13777,5207 h60
  text "REGISTRATION TOLERANCES:" at 11407.23,5202 h60
  text "METAL" at 12607,5202 h60
  text "5" at 13183.2,5202 h60
  text "3" at 14016.2,5202 h60
  text "MIL" at 14132.46,5202 h60
  text "+/-" at 13777,5089 h60
  text "HOLE SIZE TOLERANCE (UNLESS OTHERWISE SPECIFIED):" at 11407.23,5084 h60
  text "3" at 14016.2,5084 h60
  text "MIL" at 14132.46,5084 h60
  text "MATERIAL:" at 11332.46,4874.54 h60
  text "FR-4 High Tg" at 12318.9,4734.21 h60
  text "FR-408" at 11753.46,4725.64 h60
  text "OTHER" at 13241.46,4725.64 h60
  text "X" at 12164,4722 h60
  text "62 MIL (1.6mm) +/-10%" at 12073.56,4562.92 h60
  text "THICKNESS:" at 11407.23,4558.64 h60
  text "X" at 11945.4,4558.64 h60
  text "OTHER" at 13358.46,4558.64 h60
  text "TOLERANCE:" at 11407.23,4400.64 h60
  text "X" at 12246.53,4400.64 h60
  text "ANSI IPC-6012 TYPE 3 CLASS 2" at 12433.48,4400.64 h60
  text "OTHER +/-" at 12433.46,4244.64 h60
  text "BOW & TWIST:" at 11407.23,4087.64 h60
  text "X" at 12246.53,4087.64 h60
  text "ANSI IPC-6012 TYPE 3 CLASS 2" at 12433.48,4087.64 h60
  text "OTHER +/-" at 12433.46,3929.13 h60
  text "DRILLING:" at 11332.46,3790.64 h60
  text "REFERENCE:" at 11407.23,3673.64 h60
  text "X" at 12055.46,3673.64 h60
  text "AS SHOWN" at 12242.46,3673.64 h60
  text "X" at 12956.46,3673.64 h60
  text "NC_DRILL FILES" at 13093.46,3673.64 h60
  text "PTH MIN COPPER THICKNESS:" at 11407.23,3515.64 h60
  text "X" at 12757.46,3515.64 h60
  text "1MIL" at 12894.46,3515.64 h60
  text "OTHER" at 13391.46,3515.64 h60
  text "BOARD FINISH:" at 11332.46,3356.64 h60
  text "SILKSCREEN:" at 11487.68,3238.64 h60
  text "X" at 12436.46,3238.64 h60
  text "TOP" at 12562.46,3238.64 h60
  text "X" at 12946.46,3238.64 h60
  text "BOTTOM" at 13073.46,3238.64 h60
  text "SILKSCREEN COLOR:" at 11487.68,3071.64 h60
  text "X" at 12435.42,3071.64 h60
  text "WHITE" at 12562.46,3071.64 h60
  text "OTHER" at 13073.46,3071.64 h60
  text "X" at 12566.42,2912.44 h60
  text "GREEN" at 12693.46,2912.44 h60
  text "OTHER" at 13311.46,2912.44 h60
  text "SOLDER RESIST COLOR:" at 11487.68,2901.64 h60
  text "X" at 12566.42,2742.44 h60
  text "MATTE" at 12693.46,2742.44 h60
  text "SEMI-GLOSS" at 13311,2741.8 h60
  text "IMMERSION GOLD (ENIG)" at 12393.46,2553.92 h60
  text "ENEPIG" at 13731,2550.64 h60
  text "SURFACE FINISH:" at 11332.46,2549.64 h60
  text "X" at 12206.51,2549.64 h60
  text "IMM. TIN/SILVER OR EQUIV" at 11662,2392.64 h60
  text "OTHER" at 13093.46,2392.64 h60
  text "ARRAY/PANEL:" at 11332.46,2213.64 h60
  text "CUT AND TRIM PER M1 BOARD OUTLINE" at 12393.46,2209.35 h60
  text "N.C. ROUTE" at 12393.46,2057.64 h60
  text "X" at 13072.46,2057.64 h60
  text "V. SCORE" at 13259.46,2057.64 h60
  text "CERTIFICATION:" at 11332.46,1920.64 h60
  text "MATERIALS AND WORKMANSHIP FOR ALL PCBS" at 12057.46,1920.64 h60
  text "TO MEET OR EXCEED THE REQUIREMENTS OF:" at 12057.46,1822.64 h60
  text "X" at 11683.96,1686.13 h60
  text "ANSI IPC-A-600F CLASS ->" at 11822.96,1686.13 h60
  text "X" at 13462.02,1686.13 h60
  text "2" at 13580.96,1686.14 h60
  text "1" at 13265.96,1684.64 h60
  text "3" at 13934.96,1684.64 h60
  text "X" at 11686.02,1526.64 h60
  text "UL 94V-0" at 11822.96,1526.64 h60
  text "X" at 12498.02,1526.64 h60
  text "RoHS" at 12634.96,1526.64 h60
  text "OTHER" at 13279.36,1526.64 h60
  text "PER ORDER" at 13676.42,1526.64 h60
  text "ADDITIONAL REQUIREMENTS:" at 11332.46,1385.64 h60
  text "MICROSECTION:" at 11407.23,1270.64 h60
  text "YES" at 12312.96,1270.64 h60
  text "REQUIRED" at 13174.46,1114.49 h60
  text "BARE BOARD ELEC. TEST:" at 11407.23,1111.64 h60
  text "NONE" at 12712.96,1111.64 h60
  text "X" at 13047.46,1111.64 h60
  text "PER ORDER" at 13766.46,1111.64 h60
  text "MANUFACTURER'S UL:" at 11407.23,954.64 h60
  text "RAIL" at 12572.96,950.35 h60
  text "METAL" at 13064.77,950.35 h60
  text "X" at 13440,950 h60
  text "SILK" at 13576.46,950.35 h60
  text ".Layer_Name" at 577,-858.49 h60
Mechanical 11:
  lines w10: -292,-930.17 6308,-930.17 ; -292,-726.83 6310,-726.83 ; -292,-523.5 -292,-1133.5 3713,-1133.5 6310,-1133.5 6310,-523.5 -291.5,-523.5 -291.5,-1133.5 1284,-1133.5 ; 2173,-1133.5 2173,-523.5 ; 3440,-726.83 3440,-523.5 ; 4280,-726.83 4280,-523.5 ; 4902,-1140 4902,-937.17
  text "ALL ARTWORK VIEWED FROM TOP SIDE" at -228.5,-655.67 h60
  text "BOARD #:" at 2248,-655.67 h60
  text ".PRJ_Number" at 2793.5,-655.67 h60
  text "REV:" at 3638,-655.67 h60
  text ".PCB_Rev" at 3929.5,-655.67 h60
  text "SVN REV:" at 4476,-655.67 h60
  text ".VersionControl_RevNumber" at 4982,-655.67 h60
  text "LAYER NAME =" at -228.5,-858.49 h60
  text "TID #:" at 2248,-859 h60
  text ".TID" at 2793.5,-859 h60
  text "PLOT NAME =" at -228.5,-1064.34 h60
  text ".plot_File_Name" at 577,-1064.34 h60
  text "GENERATED    :" at 2250,-1064.34 h60
  text ".Print_Date" at 3119.5,-1064.34 h60
  text ".Print_Time" at 3848.5,-1064.34 h60
  text "TEXAS INSTRUMENTS" at 5113,-1064.34 h60
Mechanical 12:
  drawing of 527 lines, arcs and shapes, not listed
  text "Layer" at 8541.2,7700 h60
  text "Name" at 8951.11,7700 h60
  text "Material" at 9880.85,7700 h60
  text "Thickness" at 10740.62,7700 h60
  text "Constant" at 11390.46,7700 h60
  text "Board Layer Stack" at 11960.32,7700 h60
  text "Board Layer Stack" at 13080,7700 h60
  text "1" at 8541.2,7580 h60
  text "Top Overlay" at 8951.11,7580 h60
  text "2" at 8541.2,7460 h60
  text "Top Solder" at 8951.11,7460 h60
  text "Solder Resist" at 9880.85,7460 h60
  text "0.40mil" at 10740.62,7460 h60
  text "3.5" at 11390.46,7460 h60
  text "3" at 8541.2,7340 h60
  text "Top Layer" at 8951.11,7340 h60
  text "Copper" at 9880.85,7340 h60
  text "2.80mil" at 10740.62,7340 h60
  text "4" at 8541.2,7220 h60
  text "Dielectric" at 8951.11,7220 h60
  text "FR-4" at 9880.85,7220 h60
  text "12.00mil" at 10740.62,7220 h60
  text "4.2" at 11390.46,7220 h60
  text "5" at 8541.2,7100 h60
  text "Mid Layer" at 8951.11,7100 h60
  text "Copper" at 9880.85,7100 h60
  text "2.80mil" at 10740.62,7100 h60
  text "6" at 8541.2,6980 h60
  text "Dielectric" at 8951.11,6980 h60
  text "FR-4" at 9880.85,6980 h60
  text "34.00mil" at 10740.62,6980 h60
  text "4.2" at 11390.46,6980 h60
  text "7" at 8541.2,6860 h60
  text "GND Layer" at 8951.11,6860 h60
  text "Copper" at 9880.85,6860 h60
  text "2.80mil" at 10740.62,6860 h60
  text "8" at 8541.2,6740 h60
  text "Dielectric" at 8951.11,6740 h60
  text "FR-4" at 9880.85,6740 h60
  text "12.00mil" at 10740.62,6740 h60
  text "4.2" at 11390.46,6740 h60
  text "9" at 8541.2,6620 h60
  text "Bottom Layer" at 8951.11,6620 h60
  text "Copper" at 9880.85,6620 h60
  text "2.80mil" at 10740.62,6620 h60
  text "10" at 8541.2,6500 h60
  text "Solder Side" at 8951.11,6500 h60
  text "Solder Resist" at 9880.85,6500 h60
  text "0.40mil" at 10740.62,6500 h60
  text "3.5" at 11390.46,6500 h60
  text "11" at 8541.2,6380 h60
  text "Bottom Overlay" at 8951.11,6380 h60
  text ".Layer_Name" at 577,-858.49 h60
Mechanical 13:
  text ".Layer_Name" at 577,-858.49 h60
Mechanical 14:
  text ".Layer_Name" at 577,-858.49 h60
Mechanical 15:
  text ".Layer_Name" at 577,-858.49 h60
Mechanical 16:
  text ".Layer_Name" at 577,-858.49 h60
Drill Drawing:
  lines w10: 5156.1,4312.62 5183.73,4326.43 5211.36,4312.62 5197.54,4340.25 5211.36,4367.88 5183.73,4354.06 5156.1,4367.88 5169.91,4340.25 5156.1,4312.62 ; 5156.1,4436.95 5156.1,4450.77 5169.91,4464.58 5156.1,4478.4 5156.1,4492.22 5169.91,4492.22 5183.73,4478.4 5197.54,4492.22 5211.36,4492.22 5211.36,4478.4 5197.54,4464.58 5211.36,4450.77 5211.36,4436.95 5197.54,4436.95 5183.73,4450.77 5169.91,4436.95 5156.1,4436.95 ; 5156.1,4561.29 5211.36,4561.29 5211.36,4616.55 5156.1,4616.55 5156.1,4561.29 ; 5156.1,4699.44 5169.91,4699.44 5169.91,4685.62 5197.54,4685.62 5197.54,4699.44 5211.36,4699.44 5211.36,4727.07 5197.54,4727.07 5197.54,4740.89 5169.91,4740.89 5169.91,4727.07 5156.1,4727.07 5156.1,4699.44 ; 5156.1,4865.22 5211.36,4865.22 5183.73,4809.96 5156.1,4865.22 ; 5156.1,4948.11 5169.91,4948.11 5169.91,4934.3 5197.54,4934.3 5197.54,4948.11 5211.36,4948.11 5211.36,4975.74 5197.54,4975.74 5197.54,4989.56 5169.91,4989.56 5169.91,4975.74 5156.1,4975.74 5156.1,4948.11 ; 5156.1,5058.63 5183.73,5072.45 5211.36,5058.63 5197.54,5086.26 5211.36,5113.89 5183.73,5100.08 5156.1,5113.89 5169.91,5086.26 5156.1,5058.63 ; 5167.15,4953.64 5175.44,4953.64 5175.44,4945.35 5192.02,4945.35 5192.02,4953.64 5200.3,4953.64 5200.3,4970.21 5192.02,4970.21 5192.02,4978.5 5175.44,4978.5 5175.44,4970.21 5167.15,4970.21 5167.15,4953.64 ; 5167.15,5069.68 5183.73,5077.97 5200.3,5069.68 5192.02,5086.26 5200.3,5102.84 5183.73,5094.55 5167.15,5102.84 5175.44,5086.26 5167.15,5069.68
  lines w12: 5106,4275.32 8336.06,4275.32 ; 5106,5145.66 8336.06,5145.66 ; 5443.75,4150.98 5443.75,5270 ; 5775.56,4150.98 5775.56,5270 ; 6411.66,4150.98 6411.66,5270 ; 6670.66,4150.98 6670.66,5270 ; 7045.64,4150.98 7045.64,5270 ; 7769.86,4150.98 7769.86,5270 ; 5106,4150.98 8336.06,4150.98 8336.06,5270 5106,5270 5106,4150.98
  text "Symbol" at 5180.6,5182.97 h72
  text "Quantity" at 5481.05,5182.97 h72
  text "Finished Hole Size" at 5812.86,5182.97 h72
  text "Plated" at 6448.96,5182.97 h72
  text "Hole Type" at 6707.96,5182.97 h72
  text "Drill Layer Pair" at 7082.94,5182.97 h72
  text "Hole Tolerance" at 7807.16,5182.97 h72
  text "355" at 5481.05,5058.63 h60
  text "10.00mil (0.254mm)" at 5812.86,5058.63 h60
  text "PTH" at 6448.96,5058.63 h60
  text "Round" at 6707.96,5058.63 h60
  text "Top Layer - Bottom Layer" at 7082.94,5058.63 h60
  text "4" at 5481.05,4934.3 h60
  text "12.99mil (0.330mm)" at 5812.86,4934.3 h60
  text "PTH" at 6448.96,4934.3 h60
  text "Round" at 6707.96,4934.3 h60
  text "Top Layer - Bottom Layer" at 7082.94,4934.3 h60
  text "7" at 5481.05,4809.96 h60
  text "20.00mil (0.508mm)" at 5812.86,4809.96 h60
  text "PTH" at 6448.96,4809.96 h60
  text "Round" at 6707.96,4809.96 h60
  text "Top Layer - Bottom Layer" at 7082.94,4809.96 h60
  text "4" at 5481.05,4685.62 h60
  text "35.43mil (0.900mm)" at 5812.86,4685.62 h60
  text "PTH" at 6448.96,4685.62 h60
  text "Round" at 6707.96,4685.62 h60
  text "Top Layer - Bottom Layer" at 7082.94,4685.62 h60
  text "1" at 5481.05,4561.29 h60
  text "40.00mil (1.016mm)" at 5812.86,4561.29 h60
  text "PTH" at 6448.96,4561.29 h60
  text "Round" at 6707.96,4561.29 h60
  text "Top Layer - Bottom Layer" at 7082.94,4561.29 h60
  text "5" at 5481.05,4436.95 h60
  text "62.99mil (1.600mm)" at 5812.86,4436.95 h60
  text "PTH" at 6448.96,4436.95 h60
  text "Round" at 6707.96,4436.95 h60
  text "Top Layer - Bottom Layer" at 7082.94,4436.95 h60
  text "4" at 5481.05,4312.62 h60
  text "140.00mil (3.556mm)" at 5812.86,4312.62 h60
  text "PTH" at 6448.96,4312.62 h60
  text "Round" at 6707.96,4312.62 h60
  text "Top Layer - Bottom Layer" at 7082.94,4312.62 h60
  text "380 Total" at 5481.05,4188.28 h60
  text ".Layer_Name" at 577,-858.49 h60

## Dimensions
0,-400 to 1000,-400 on Mechanical 2
2240,1390 to 4760,1390 on Mechanical 1
2240,1390 to 2240,4080 on Mechanical 1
